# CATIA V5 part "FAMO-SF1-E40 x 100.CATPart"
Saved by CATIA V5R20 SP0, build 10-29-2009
Part number: FAMO-SF1-E40 x 100
Definition: NONE
Nomenclature: FAMO-SF1-E40 x 100
Source: Unknown
Description: FAMO-SF1-E40 x 100
Bounding box of the stored display mesh (mm): x -70 to 30, y -31.5 to 31.5, z -31.5 to 31.5
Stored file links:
  C:\Users\Utente\Desktop\IO LAVORO\3D X SITO CF\X SITO\FAMO\FAMO-SF1-E40 x 100.CATPart
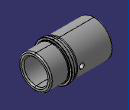
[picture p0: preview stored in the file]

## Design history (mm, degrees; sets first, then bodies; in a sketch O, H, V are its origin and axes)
Body1 "FAMO-SF1-E40 x 100" (main body)
  Solid1: solid without history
